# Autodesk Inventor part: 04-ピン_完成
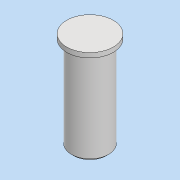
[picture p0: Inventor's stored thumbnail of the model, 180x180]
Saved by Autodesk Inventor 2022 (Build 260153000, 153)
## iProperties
Created: 2021-07
Part Number: 04-ピン_完成
Material: 一般
Document SubType Name: Modeling
Designer: DesignLab
Density: 1 g/cm^3
Appearance: 既定
Author: DesignLab
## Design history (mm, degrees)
sketch "スケッチ1"
  geometry: C1 r 4 at (4.73, 0) reference; 1 further point
  node "参照1"
node "作業平面1"
extrude "押し出し1" new body sketch "スケッチ1" stored distance "d0" = 10; taper "d1" = 0 deg
sketch "スケッチ2"
  geometry: C1 r 4 at (0, 0) reference; C2 r 5 at (0, 0)
  constraints: 1 centre point, 1 coincident
  dimensions: "d2" = 10 diameter of C2
extrude "押し出し2" join sketch "スケッチ2" distance "d3" = 1; taper "d4" = 0 deg
chamfer "面取り1" distance "d5" = 0.5; stored, may be unused: second distance "d6" = 2, angle "d7" = 45 deg
node "ソリッド1"
node "投影ループ1"
